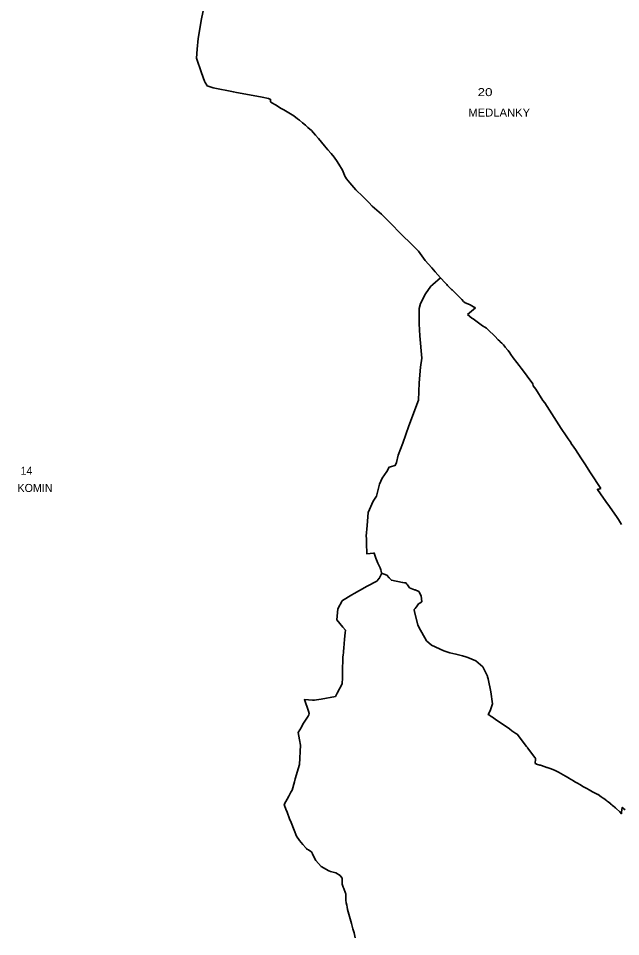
# Model space of a CAD drawing. Extents: x -610940 to -588976, y -1170376 to -1149800.
# Drawn here: x -602079 to -600196, y -1157770 to -1154902 of the extents above; entities that cross this region are included whole.
import ezdxf

# ---------------------------------------------------------------- set-up
doc = ezdxf.new("R2010")
doc.units = 0
doc.header["$LTSCALE"] = 10
doc.layers.add('54', color=7, linetype='Continuous', lineweight=35)
doc.layers.add('55', color=7, linetype='Continuous')
doc.layers.add('56', color=7, linetype='Continuous')

msp = doc.modelspace()

# ---------------------------------------------------------------- linework, layer by layer
at = {"layer": '54'}
for p, q in [((-600758.97, -1155712.33), (-600744.62, -1155728.59)), ((-600739.79, -1155734.06), (-600744.62, -1155728.59)), ((-600739.79, -1155734.06), (-600737.28, -1155736.91)), ((-600737.28, -1155736.91), (-600724.89, -1155748.93)), ((-600723.45, -1155750.32), (-600724.89, -1155748.93)), ((-600649.77, -1155806.27), (-600675.22, -1155827.09)), ((-600667.24, -1155797.57), (-600656.56, -1155802.92)), ((-600675.22, -1155827.09), (-600661.15, -1155838.6)), ((-600657.89, -1155841.26), (-600661.15, -1155838.6)), ((-600657.89, -1155841.26), (-600640.46, -1155853.24)), ((-600640.46, -1155853.24), (-600636.83, -1155855.96)), ((-600628.58, -1155862.14), (-600636.83, -1155855.96)), ((-600628.58, -1155862.14), (-600620.47, -1155866.96)), ((-600616.02, -1155869.6), (-600620.47, -1155866.96)), ((-600616.02, -1155869.6), (-600604.88, -1155880.03)), ((-600594.41, -1155889.83), (-600604.88, -1155880.03)), ((-600594.41, -1155889.83), (-600589.24, -1155895.44)), ((-600578.96, -1155906.59), (-600589.24, -1155895.44)), ((-600578.96, -1155906.59), (-600574.4, -1155910.99)), ((-600572.88, -1155912.46), (-600574.4, -1155910.99)), ((-600568.11, -1155917), (-600565.69, -1155919.3)), ((-600564.91, -1155920.05), (-600565.69, -1155919.3)), ((-600557.1, -1155929.24), (-600548.68, -1155939.15)), ((-600548.41, -1155939.47), (-600548.68, -1155939.15)), ((-600548.41, -1155939.47), (-600546.4, -1155942.35)), ((-600545.15, -1155944.12), (-600545.1, -1155944.19)), ((-600537.32, -1155955.31), (-600545.1, -1155944.19)), ((-600537.32, -1155955.31), (-600534.21, -1155959.58)), ((-600532.05, -1155962.54), (-600534.21, -1155959.58)), ((-600513.99, -1155986.09), (-600507.49, -1155994.57)), ((-600496.5, -1156008.89), (-600507.49, -1155994.57)), ((-600496.5, -1156008.89), (-600488.24, -1156020.28)), ((-600203.4, -1156467.99), (-600193.54, -1156482.97)), ((-600990.55, -1156545.31), (-600990.71, -1156538.05)), ((-600946.12, -1156625.14), (-600947.58, -1156618.22)), ((-600945.36, -1156628.72), (-600946.12, -1156625.14)), ((-600827.29, -1156692.17), (-600838.39, -1156687.64)), ((-600835.95, -1156741.45), (-600839.11, -1156745.52)), ((-600841.28, -1156748.3), (-600839.11, -1156745.52)), ((-600690.69, -1156893.28), (-600679.82, -1156896.45)), ((-600673.83, -1156898.2), (-600679.82, -1156896.45)), ((-600620.22, -1156942.47), (-600627.31, -1156927.74)), ((-600620.22, -1156942.47), (-600612.88, -1156957.27)), ((-600612.19, -1156958.65), (-600612.88, -1156957.27)), ((-600597.26, -1157085.27), (-600600.93, -1157082.73)), ((-600597.26, -1157085.27), (-600588.57, -1157091.22)), ((-600588.57, -1157091.22), (-600544.02, -1157121.77)), ((-600536.18, -1157127.15), (-600544.02, -1157121.77)), ((-600536.18, -1157127.15), (-600524.1, -1157135.47)), ((-600520.02, -1157138.28), (-600524.1, -1157135.47)), ((-600464.11, -1157229.4), (-600462.43, -1157215.25)), ((-600460.4, -1157230.63), (-600464.11, -1157229.4)), ((-600462.24, -1157213.63), (-600462.43, -1157215.25)), ((-600443.81, -1157235.9), (-600446.92, -1157234.88)), ((-600333.6, -1157289.88), (-600339.78, -1157286.58)), ((-600322.34, -1157295.89), (-600333.6, -1157289.88)), ((-600256.92, -1157333.27), (-600250.87, -1157337.54)), ((-600248.73, -1157339.05), (-600250.87, -1157337.54)), ((-600248.73, -1157339.05), (-600245.21, -1157341.62)), ((-600243.44, -1157342.92), (-600245.21, -1157341.62)), ((-600240.38, -1157345.16), (-600243.44, -1157342.92)), ((-600240.38, -1157345.16), (-600238.24, -1157346.94)), ((-600235.96, -1157348.82), (-600238.24, -1157346.94)), ((-600235.96, -1157348.82), (-600231.09, -1157352.85)), ((-600230.32, -1157352.97), (-600231.09, -1157352.85)), ((-600230.32, -1157352.97), (-600230.39, -1157353.42)), ((-600230.39, -1157353.42), (-600228.49, -1157354.97)), ((-600228.06, -1157355.32), (-600228.49, -1157354.97))]:
    msp.add_line(p, q, dxfattribs=at)
for points in [[(-601499.41, -1154869.95), (-601506.4, -1154904.12), (-601516.45, -1154964.93), (-601520.52, -1154998.58), (-601522.42, -1155026.58), (-601506.24, -1155072.43), (-601497.2, -1155098.1), (-601494.54, -1155102.99), (-601490.3, -1155111.24), (-601489.14, -1155113.51), (-601469.73, -1155118.96), (-601406.74, -1155131.93), (-601397.52, -1155133.73), (-601344.61, -1155143.55), (-601316.66, -1155148.7), (-601297, -1155152.32), (-601290.51, -1155155.49), (-601290.5, -1155155.97), (-601290.5, -1155160.27), (-601290.43, -1155162.85), (-601286.34, -1155166.02), (-601275.13, -1155172.64), (-601257.1, -1155183.68), (-601249.43, -1155188.37), (-601217.75, -1155207.12), (-601206.31, -1155216.25), (-601199.75, -1155220.5), (-601190.62, -1155228.25), (-601181.75, -1155236.12), (-601173.62, -1155243.25), (-601162.44, -1155252.87), (-601149.94, -1155267), (-601140.37, -1155277.75), (-601130.95, -1155289.4)], [(-601130.95, -1155289.4), (-601122.19, -1155300.25), (-601111.43, -1155313), (-601101.44, -1155324.62), (-601091.87, -1155335.75), (-601082.52, -1155349.74), (-601082.44, -1155349.87), (-601073.68, -1155363), (-601068.81, -1155371.75), (-601066.12, -1155376.62), (-601060, -1155391.62), (-601059.19, -1155393.12), (-601053.5, -1155404), (-601043.31, -1155416.12), (-601024.37, -1155438.25), (-601002.69, -1155459), (-600983.81, -1155477.62), (-600973.44, -1155488.87), (-600944.06, -1155513.5), (-600928.87, -1155528.25), (-600918.62, -1155538.87), (-600907.88, -1155550), (-600891.69, -1155566.62), (-600875.68, -1155583), (-600872.12, -1155586.88), (-600859.75, -1155598.62), (-600855.56, -1155602.62), (-600848.31, -1155609.37), (-600838.62, -1155618.75), (-600833.24, -1155624.63), (-600831.53, -1155626.58), (-600828.75, -1155629.25), (-600807.25, -1155658.75), (-600786.87, -1155681.12), (-600775.74, -1155693.64), (-600758.97, -1155712.33)], [(-600805.86, -1155762.76), (-600789.33, -1155738.8), (-600784.73, -1155734.92), (-600783.77, -1155734.04), (-600758.97, -1155712.33)], [(-600828.65, -1156095.16), (-600826.58, -1156041.03), (-600821.66, -1155991.32), (-600817.42, -1155963.54), (-600824.38, -1155894.37), (-600826.51, -1155856.19), (-600826.36, -1155808.87), (-600822.28, -1155793.42), (-600805.86, -1155762.76)], [(-600723.45, -1155750.32), (-600703.47, -1155770.38), (-600693.09, -1155780.55), (-600687.15, -1155786.34), (-600681.99, -1155790.49), (-600678.78, -1155792.03), (-600667.24, -1155797.57)], [(-600649.77, -1155806.27), (-600651.84, -1155805.25), (-600653.81, -1155804.28), (-600656.56, -1155802.92)], [(-600568.11, -1155917), (-600568.28, -1155916.84), (-600572.88, -1155912.46)], [(-600564.91, -1155920.05), (-600563.03, -1155922.26), (-600559.66, -1155926.23), (-600557.1, -1155929.24)], [(-600545.15, -1155944.12), (-600545.26, -1155943.96), (-600545.32, -1155943.87), (-600546.4, -1155942.35)], [(-600532.05, -1155962.54), (-600520.69, -1155977.35), (-600513.99, -1155986.09)], [(-600488.24, -1156020.28), (-600471.02, -1156044.15), (-600469.51, -1156049.7), (-600461.6, -1156060.75), (-600439.18, -1156095.51)], [(-600902.27, -1156298.93), (-600900.75, -1156298.44), (-600897.18, -1156289.79), (-600891.6, -1156266.1), (-600877.13, -1156229.36), (-600858.29, -1156175.37), (-600828.65, -1156095.16)], [(-600439.18, -1156095.51), (-600433.84, -1156103.52), (-600382.23, -1156183.11)], [(-600382.23, -1156183.11), (-600366.43, -1156206.48), (-600360.47, -1156215.59), (-600354.72, -1156224.22), (-600348.79, -1156233.13), (-600348.06, -1156234.2), (-600338.06, -1156249.35), (-600320.89, -1156275.19), (-600308.57, -1156293.84)], [(-600991.31, -1156519.5), (-600988.92, -1156486.09), (-600985.43, -1156445.9), (-600969.74, -1156410.51), (-600959.34, -1156394.74), (-600950.17, -1156356.85), (-600942.11, -1156338.92), (-600927.72, -1156317.38), (-600920.16, -1156303.83), (-600916.07, -1156302.7), (-600902.27, -1156298.93)], [(-600308.57, -1156293.84), (-600290.29, -1156321.87), (-600258.41, -1156370.4)], [(-600258.41, -1156370.4), (-600264.3, -1156372.29), (-600266.84, -1156373.06), (-600268.87, -1156373.67), (-600250.09, -1156400.63)], [(-600250.09, -1156400.63), (-600237.65, -1156418.35), (-600236.68, -1156419.74), (-600224.49, -1156437.11)], [(-600224.49, -1156437.11), (-600207.59, -1156461.62), (-600203.4, -1156467.99)], [(-600990.71, -1156538.05), (-600991.06, -1156526.63), (-600991.31, -1156519.5)], [(-600968.85, -1156572.56), (-600989.96, -1156574.63), (-600989.79, -1156570.74), (-600990.55, -1156545.31)], [(-600947.58, -1156618.22), (-600955.4, -1156603.39), (-600961.82, -1156588.26), (-600966.65, -1156572.29), (-600968.85, -1156572.56)], [(-600943.98, -1156635.2), (-600944.33, -1156637.04), (-600944.88, -1156639.6), (-600951.64, -1156651.3), (-600952.08, -1156652.05), (-600953.25, -1156653.61), (-600958.07, -1156660.01), (-600988.22, -1156676.15), (-600988.42, -1156676.13), (-601013.08, -1156689.64), (-601029.76, -1156698.74), (-601036.9, -1156702.7), (-601052.07, -1156712.35), (-601053.54, -1156713.27), (-601062.22, -1156718.81), (-601066.86, -1156721.76), (-601079.88, -1156746.63), (-601083.29, -1156781.36), (-601064.27, -1156804.21), (-601056.62, -1156813.58), (-601057.01, -1156821.66), (-601059.02, -1156840.84), (-601059.28, -1156843.72), (-601060.17, -1156853.32), (-601061.92, -1156870.33), (-601062.55, -1156878.17), (-601063.09, -1156883.87), (-601063.71, -1156889.85), (-601064.19, -1156892.83), (-601064.35, -1156894.42), (-601065.1, -1156912.32), (-601065.82, -1156929.02), (-601066.02, -1156933.5), (-601066.17, -1156936.88), (-601065.94, -1156940.43), (-601065.39, -1156949.29), (-601065.27, -1156951.04), (-601065.57, -1156955.4), (-601065.81, -1156959.11), (-601066.23, -1156966.34)], [(-600919.65, -1156649.84), (-600926.73, -1156641.82), (-600943.98, -1156635.2), (-600945.36, -1156628.72)], [(-600872.4, -1156664.84), (-600878.22, -1156663.73), (-600913.1, -1156657.28), (-600917.98, -1156651.86), (-600919.65, -1156649.84)], [(-600864.83, -1156669.05), (-600867.36, -1156665.77), (-600872.4, -1156664.84)], [(-600838.39, -1156687.64), (-600840.63, -1156686.76), (-600855.97, -1156680.43), (-600862.84, -1156671.54), (-600864.83, -1156669.05)], [(-600835.95, -1156741.45), (-600834.65, -1156739.76), (-600827.84, -1156730.83), (-600826.03, -1156729.58), (-600817.97, -1156724.4), (-600820.09, -1156706.26), (-600827.29, -1156692.17)], [(-600690.69, -1156893.28), (-600711.2, -1156888.05), (-600729.83, -1156883.75), (-600748.97, -1156877.84), (-600787.59, -1156859.87), (-600803.17, -1156846.34), (-600826.84, -1156804.14), (-600829.87, -1156796.09), (-600840.52, -1156756.25), (-600841.28, -1156748.3)], [(-600627.31, -1156927.74), (-600649.26, -1156908.84), (-600673.83, -1156898.2)], [(-601066.23, -1156966.34), (-601066.89, -1156976.32), (-601067.25, -1156981.08), (-601082.79, -1157010.06), (-601087.88, -1157019.84), (-601132.76, -1157028.23), (-601153.89, -1157032.18), (-601159.18, -1157032.15), (-601184.64, -1157029.68), (-601172.08, -1157066.28), (-601169.63, -1157073.41), (-601171.3, -1157077.85), (-601172.04, -1157079.11), (-601173.38, -1157081.28), (-601189.47, -1157107.18), (-601194.32, -1157115.61), (-601204.19, -1157132.48), (-601200.05, -1157155.68), (-601197.46, -1157171.8), (-601200.28, -1157232.65), (-601213.31, -1157277.33), (-601215.81, -1157286.46), (-601223.6, -1157313.23), (-601227, -1157319.32), (-601233.62, -1157331.05), (-601248.37, -1157357.27), (-601241.49, -1157375.24), (-601241, -1157376.64), (-601239.06, -1157381.71), (-601231.32, -1157401.87), (-601226.38, -1157413.85), (-601217.23, -1157437.41), (-601209.96, -1157456.3), (-601200.07, -1157470.24), (-601190.05, -1157482.22), (-601180.28, -1157493.23), (-601178.67, -1157495.26), (-601176.76, -1157497.51), (-601171.89, -1157499.41), (-601170.72, -1157499.94)], [(-600600.93, -1157082.73), (-600606.7, -1157078.78), (-600610.04, -1157076.56), (-600603.85, -1157065.47), (-600596.99, -1157042.82), (-600602.11, -1157005.5), (-600610.87, -1156965.05), (-600612.19, -1156958.65)], [(-600464.64, -1157210.51), (-600487.63, -1157180.12), (-600488.02, -1157179.52), (-600490.77, -1157176.01), (-600520.02, -1157138.28)], [(-600462.24, -1157213.63), (-600463.74, -1157211.66), (-600464.64, -1157210.51)], [(-600446.92, -1157234.88), (-600448.94, -1157234.24), (-600458.95, -1157231.14), (-600460.4, -1157230.63)], [(-600339.78, -1157286.58), (-600343.85, -1157284.12), (-600358.19, -1157275.24), (-600359.94, -1157274.11), (-600368.97, -1157268.63), (-600390.99, -1157256.4), (-600401.38, -1157251.16), (-600413.66, -1157246.31), (-600426.05, -1157241.92), (-600426.65, -1157241.53), (-600443.81, -1157235.9)], [(-600256.92, -1157333.27), (-600266.73, -1157326.52), (-600267.34, -1157326.1), (-600275.87, -1157322.02), (-600284.58, -1157317.98), (-600294.65, -1157312.17), (-600302.61, -1157307.7), (-600314.34, -1157301.08), (-600322.34, -1157295.89)], [(-600199.32, -1157380.52), (-600200.36, -1157379.51), (-600209.15, -1157370.96), (-600212.47, -1157368.07), (-600214.21, -1157366.55), (-600214.74, -1157366.09), (-600218.07, -1157363.39), (-600221.44, -1157360.67), (-600224.44, -1157358.25), (-600228.06, -1157355.32)], [(-600182.59, -1157373.76), (-600191.53, -1157366.84), (-600193.46, -1157381.58), (-600193.92, -1157386.42), (-600199.32, -1157380.52)], [(-601170.72, -1157499.94), (-601162.96, -1157505.53), (-601159.57, -1157512.07), (-601157.19, -1157516.58), (-601149.2, -1157532.21), (-601132.34, -1157550.74), (-601108.76, -1157565.17), (-601103.16, -1157566.76), (-601086.25, -1157571.36), (-601073.08, -1157579.58), (-601071.02, -1157582.48), (-601066.85, -1157587.5), (-601066.62, -1157595.74), (-601066.74, -1157603.37), (-601066.75, -1157606.6), (-601065.49, -1157609.12), (-601063.23, -1157615.25), (-601061.79, -1157619.48), (-601056.19, -1157634.14), (-601055.86, -1157635.54), (-601055.42, -1157643.37), (-601055.45, -1157645.03), (-601055.47, -1157652.61), (-601055.29, -1157658.19), (-601054.38, -1157662.59), (-601053.96, -1157664.47), (-601052.39, -1157671.51), (-601050.95, -1157678.57), (-601049.77, -1157685.04), (-601043.39, -1157707.86), (-601037.17, -1157729.24), (-601033.07, -1157745.39), (-601029.74, -1157758.56), (-601025.69, -1157774.47)]]:
    msp.add_lwpolyline(points, dxfattribs=at)

# ---------------------------------------------------------------- texts
at = {"layer": '55', "width": 1.05}
msp.add_text('MEDLANKY ', height=25, dxfattribs=at).set_placement((-600672.55, -1155209.06))
at = {"layer": '55'}
msp.add_text('KOMIN ', height=25, dxfattribs=at).set_placement((-602081.66, -1156381.45))
at = {"layer": '56', "width": 1.25}
msp.add_text('20 ', height=25, dxfattribs=at).set_placement((-600643.52, -1155145.28))
at = {"layer": '56'}
msp.add_text('14 ', height=25, dxfattribs=at).set_placement((-602072.14, -1156327.75))

doc.saveas('drawing.dxf')
